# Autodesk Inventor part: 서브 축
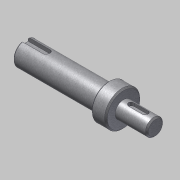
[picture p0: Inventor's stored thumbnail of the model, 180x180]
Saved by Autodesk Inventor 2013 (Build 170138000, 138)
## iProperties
Created: 2016-04
Part Number: 서브 축
Document SubType Name: Modeling
Designer: mdu
Density: 1 g/cm^3
Mass: 19.9624 g
Surface Area: 57.7178 cm^2
Volume: 19.9624 cm^3
Material: 강철, 연강
Author: mdu
Revision Number: 1
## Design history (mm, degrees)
sketch "스케치1"
  geometry: L1 (-16.331, 0)-(-108.831, 0); L2 (-16.331, 0)-(-16.331, -6); L3 (-16.331, -6)-(-38.831, -6); L4 (-38.831, -12.5)-(-46.5, -12.5); L5 (-46.5, -8.5)-(-108.831, -8.5); L6 (-108.831, -8.5)-(-108.831, 0); L7 (-46.5, -8.5)-(-46.5, -12.5); L8 (-38.831, -6)-(-38.831, -12.5); L9 (-46.5, 12.249)-(-46.5, -12.249) reference; L10 (-38.831, -17)-(-38.831, 17) reference; 2 further points
  constraints: 17 end point, 4 perpendicular, 2 collinear, 2 parallel, 1 horizontal, 1 midpoint, 1 point on line
  dimensions: "d1" = 12 diameter of L3 L1; "d2" = 25 diameter of L4 L1; "d3" = 17 diameter of L5 L1; "d18" = 22.5 distance of L2.end L3.end; "d20" = 70 distance between parallel lines of L6 L8; "d21" = 7.66872 distance of L4.start L4.end (derived)
revolve "회전1" sketch "스케치1" stored, may be unused: angle "d5" = 90 deg
chamfer "모따기1" distance "d6" = 1; stored, may be unused: second distance "d7" = 2, angle "d8" = 45 deg
node "작업 평면1"
sketch "스케치2"
  geometry: L1 (11.25, 5)-(11.25, -5) reference; L2 (-5.75, -2)-(4.25, -2); L3 (4.25, 2)-(-5.75, 2); A1 r 2 centre (4.25, 0) between (4.25, -2) and (4.25, 2); A2 r 2 centre (-5.75, 0) between (-5.75, 2) and (-5.75, -2); 2 further points
  constraints: 4 end point, 4 point on circle, 4 tangent, 2 centre point, 1 horizontal alignment, 1 midpoint, 1 parallel, 1 perpendicular
  dimensions: "d9" = 4 distance between parallel lines of L2 L3; "d10" = 14 dimension on A1 A2; "d11" = 5 distance edge to line of A1 L1
extrude "돌출1" cut sketch "스케치2" distance "d12" = 2.5; taper "d13" = 0 deg
node "작업 평면2"
sketch "스케치3"
  geometry: L1 (-31.166, -7.5)-(-31.166, 7.5) reference; L2 (-31.166, 2.5)-(-15.666, 2.5); L3 (-15.666, -2.5)-(-31.166, -2.5); A1 r 2.5 centre (-15.666, 0) between (-15.666, -2.5) and (-15.666, 2.5); 2 further points
  constraints: 4 end point, 2 perpendicular, 2 point on circle, 2 point on line, 2 tangent, 1 centre point, 1 horizontal alignment, 1 midpoint
  dimensions: "d14" = 5 distance between parallel lines of L3 L2; "d15" = 18 dimension on A1 L1
extrude "돌출2" cut sketch "스케치3" distance "d16" = 3; taper "d17" = 0 deg
sketch "스케치4"
  geometry: C1 r 12.5 at (0, 0) reference; 1 further point
extrude "돌출3" join sketch "스케치4" distance "d22" = 3; taper "d23" = 0 deg
chamfer "모따기2" distance "d24" = 1; stored, may be unused: second distance "d25" = 2, angle "d26" = 45 deg
node "솔리드1"
node "참조4"
node "참조5"
